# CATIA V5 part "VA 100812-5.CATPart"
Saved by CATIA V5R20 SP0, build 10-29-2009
Part number: VA 100812-5
Revision: ANY
Definition: UNKNOWN
Nomenclature: VA 100812-5
Source: Unknown
Bounding box of the stored display mesh (mm): x -3.804 to 3.804, y 0.1 to 1.6, z -4 to 4
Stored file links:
  C:\Users\Utente\Desktop\IO LAVORO\3D X SITO CF\CUMSA\3D files VA\VA 100812\VA 100812-5.CATPart
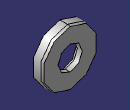
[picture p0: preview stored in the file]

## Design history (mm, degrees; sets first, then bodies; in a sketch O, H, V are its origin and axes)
Body1 "Cortar-Extruir1" (main body)
  Solid1: solid without history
